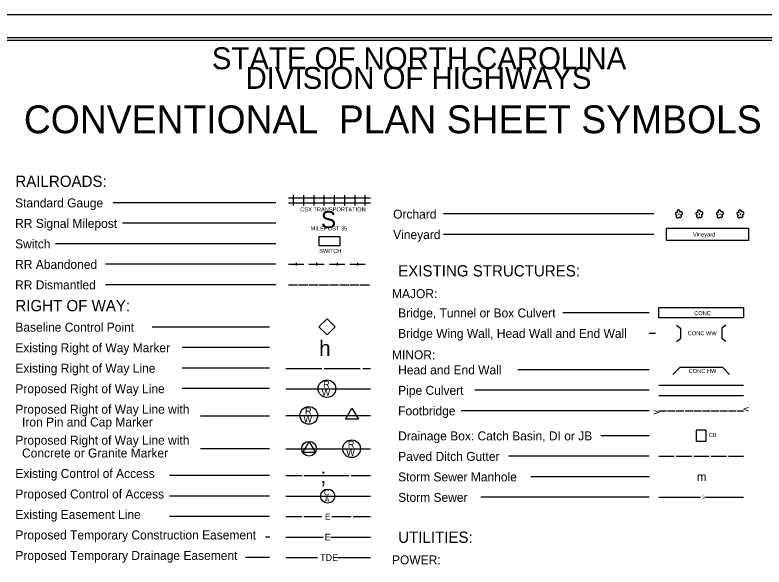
# Model space of a CAD drawing. Extents: x 573853.5 to 573887.1, y -53276.2 to -53254.2.
# Drawn here: x 573864.68 to 573879.29, y -53264.98 to -53254.2 of the extents above; entities that cross this region are included whole.
import ezdxf

# ---------------------------------------------------------------- set-up
doc = ezdxf.new("R2010")
doc.units = 0
for name, color, linetype in [('Default', 7, 'Continuous'), ('Sheet Cutting Line CELL', 7, 'Continuous'), ('Sheet Plot Border Inside CELL', 7, 'Continuous'), ('Sheet Plot Border Outside CELL', 7, 'Continuous'), ('Sheet Symbology CELL', 7, 'Continuous')]:
    doc.layers.add(name, color=color, linetype=linetype)

msp = doc.modelspace()

# ---------------------------------------------------------------- linework, layer by layer
at = {"layer": 'Default'}
msp.add_lwpolyline([(573870.609, -53260.29), (573870.766, -53260.133), (573870.922, -53260.29), (573870.766, -53260.446)], close=True, dxfattribs=at)
at = {"layer": 'Sheet Cutting Line CELL'}
msp.add_line((573887.133, -53254.201), (573853.453, -53254.201), dxfattribs=at)
at = {"layer": 'Sheet Plot Border Inside CELL'}
msp.add_lwpolyline([(573853.713, -53275.752), (573887.043, -53275.752), (573887.043, -53254.65), (573853.713, -53254.65)], close=True, dxfattribs=at)
at = {"layer": 'Sheet Plot Border Outside CELL'}
msp.add_lwpolyline([(573853.453, -53276.201), (573887.133, -53276.201), (573887.133, -53254.201), (573853.453, -53254.201)], close=True, dxfattribs=at)
at = {"layer": 'Sheet Symbology CELL'}
for p, q in [((573870.013, -53257.771), (573870.213, -53257.771)), ((573870.113, -53257.921), (573870.113, -53257.721)), ((573870.213, -53257.771), (573870.413, -53257.771)), ((573870.313, -53257.921), (573870.313, -53257.721)), ((573870.413, -53257.771), (573870.613, -53257.771)), ((573870.513, -53257.921), (573870.513, -53257.721)), ((573870.613, -53257.771), (573870.813, -53257.771)), ((573870.713, -53257.921), (573870.713, -53257.721)), ((573870.813, -53257.771), (573871.013, -53257.771)), ((573870.913, -53257.921), (573870.913, -53257.721)), ((573871.013, -53257.771), (573871.213, -53257.771)), ((573871.113, -53257.921), (573871.113, -53257.721)), ((573871.213, -53257.771), (573871.413, -53257.771)), ((573871.313, -53257.921), (573871.313, -53257.721)), ((573871.413, -53257.771), (573871.613, -53257.771)), ((573871.513, -53257.921), (573871.513, -53257.721)), ((573869.765, -53257.866), (573866.597, -53257.866)), ((573870.013, -53257.871), (573870.213, -53257.871)), ((573870.213, -53257.871), (573870.413, -53257.871)), ((573870.413, -53257.871), (573870.613, -53257.871)), ((573870.613, -53257.871), (573870.813, -53257.871)), ((573870.813, -53257.871), (573871.013, -53257.871)), ((573871.013, -53257.871), (573871.213, -53257.871)), ((573871.213, -53257.871), (573871.413, -53257.871)), ((573871.413, -53257.871), (573871.613, -53257.871)), ((573877.139, -53258.085), (573873.041, -53258.085)), ((573869.765, -53258.266), (573866.774, -53258.266)), ((573877.139, -53258.485), (573873.041, -53258.485)), ((573869.765, -53258.666), (573865.467, -53258.666)), ((573869.765, -53259.066), (573866.442, -53259.066)), ((573870.013, -53259.066), (573870.313, -53259.066)), ((573870.163, -53259.041), (573870.163, -53259.091)), ((573870.413, -53259.066), (573870.713, -53259.066)), ((573870.563, -53259.041), (573870.563, -53259.091)), ((573870.813, -53259.066), (573871.113, -53259.066)), ((573870.963, -53259.041), (573870.963, -53259.091)), ((573871.213, -53259.066), (573871.513, -53259.066)), ((573871.363, -53259.041), (573871.363, -53259.091)), ((573869.765, -53259.466), (573866.442, -53259.466)), ((573869.765, -53259.466), (573866.442, -53259.466)), ((573870.013, -53259.466), (573870.193, -53259.466)), ((573870.213, -53259.466), (573870.393, -53259.466)), ((573870.413, -53259.466), (573870.593, -53259.466)), ((573870.613, -53259.466), (573870.793, -53259.466)), ((573870.813, -53259.466), (573870.993, -53259.466)), ((573871.013, -53259.466), (573871.193, -53259.466)), ((573871.213, -53259.466), (573871.393, -53259.466)), ((573871.413, -53259.466), (573871.593, -53259.466)), ((573877.053, -53260.014), (573875.365, -53260.014)), ((573869.642, -53260.293), (573867.358, -53260.293)), ((573877.582, -53260.257), (573877.664, -53260.314)), ((573877.664, -53260.314), (573877.664, -53260.514)), ((573878.546, -53260.257), (573878.464, -53260.314)), ((573878.464, -53260.314), (573878.464, -53260.514)), ((573877.053, -53260.414), (573877.173, -53260.414)), ((573877.582, -53260.572), (573877.664, -53260.514)), ((573878.546, -53260.572), (573878.464, -53260.514)), ((573869.642, -53260.693), (573867.943, -53260.693)), ((573869.642, -53261.093), (573867.943, -53261.093)), ((573869.963, -53261.105), (573870.663, -53261.105)), ((573870.713, -53261.105), (573871.413, -53261.105)), ((573871.463, -53261.105), (573871.613, -53261.105)), ((573877.053, -53261.126), (573874.487, -53261.126)), ((573877.51, -53261.217), (573877.652, -53261.076)), ((573877.652, -53261.076), (573878.477, -53261.076)), ((573878.477, -53261.076), (573878.618, -53261.217)), ((573869.642, -53261.493), (573867.943, -53261.493)), ((573869.963, -53261.496), (573871.613, -53261.496)), ((573877.239, -53261.426), (573878.889, -53261.426)), ((573877.053, -53261.526), (573873.649, -53261.526)), ((573877.239, -53261.626), (573878.889, -53261.626)), ((573877.053, -53261.926), (573873.384, -53261.926)), ((573877.239, -53261.926), (573877.389, -53261.926)), ((573877.409, -53261.926), (573877.559, -53261.926)), ((573877.579, -53261.926), (573877.729, -53261.926)), ((573877.749, -53261.926), (573877.899, -53261.926)), ((573877.919, -53261.926), (573878.069, -53261.926)), ((573878.089, -53261.926), (573878.239, -53261.926)), ((573878.259, -53261.926), (573878.409, -53261.926)), ((573878.429, -53261.926), (573878.579, -53261.926)), ((573878.599, -53261.926), (573878.749, -53261.926)), ((573878.769, -53261.926), (573878.889, -53261.926)), ((573869.642, -53262.03), (573868.3, -53262.03)), ((573869.963, -53262.018), (573871.613, -53262.018)), ((573871.252, -53262.018), (573871.252, -53262.018)), ((573877.053, -53262.414), (573876.109, -53262.414)), ((573869.642, -53262.671), (573868.3, -53262.671)), ((573869.963, -53262.668), (573871.613, -53262.668)), ((573870.417, -53262.668), (573870.417, -53262.668)), ((573877.053, -53262.814), (573874.314, -53262.814)), ((573877.239, -53262.814), (573877.539, -53262.814)), ((573877.579, -53262.814), (573877.879, -53262.814)), ((573877.919, -53262.814), (573878.219, -53262.814)), ((573878.259, -53262.814), (573878.559, -53262.814)), ((573878.599, -53262.814), (573878.889, -53262.814)), ((573869.642, -53263.193), (573867.691, -53263.193)), ((573869.963, -53263.193), (573870.272, -53263.193)), ((573870.312, -53263.193), (573871.2, -53263.193)), ((573871.24, -53263.193), (573871.613, -53263.193)), ((573877.053, -53263.214), (573874.74, -53263.214)), ((573869.642, -53263.593), (573867.691, -53263.593)), ((573869.963, -53263.593), (573871.613, -53263.593)), ((573877.053, -53263.614), (573873.769, -53263.614)), ((573877.239, -53263.614), (573878.05, -53263.614)), ((573878.15, -53263.614), (573878.889, -53263.614)), ((573869.642, -53263.993), (573867.691, -53263.993)), ((573869.963, -53263.993), (573870.273, -53263.993)), ((573870.313, -53263.993), (573870.663, -53263.993)), ((573870.863, -53263.993), (573871.238, -53263.993)), ((573871.278, -53263.993), (573871.613, -53263.993)), ((573869.65, -53264.393), (573869.566, -53264.393)), ((573869.963, -53264.393), (573870.015, -53264.393)), ((573870.015, -53264.393), (573870.69, -53264.393)), ((573870.84, -53264.393), (573871.515, -53264.393)), ((573871.515, -53264.393), (573871.613, -53264.393)), ((573869.642, -53264.793), (573869.179, -53264.793)), ((573869.963, -53264.793), (573870.03, -53264.793)), ((573870.03, -53264.793), (573870.58, -53264.793)), ((573870.98, -53264.793), (573871.53, -53264.793)), ((573871.53, -53264.793), (573871.613, -53264.793))]:
    msp.add_line(p, q, dxfattribs=at)
for points in [[(573886.793, -53254.701), (573856.793, -53254.701), (573856.793, -53275.68), (573886.793, -53275.68)], [(573870.613, -53258.527), (573871.013, -53258.527), (573871.013, -53258.709), (573870.613, -53258.709)], [(573871.127, -53262.09), (573871.252, -53261.874), (573871.377, -53262.09)], [(573877.968, -53262.521), (573878.16, -53262.521), (573878.16, -53262.308), (573877.968, -53262.308)], [(573870.292, -53262.74), (573870.417, -53262.524), (573870.542, -53262.74)]]:
    msp.add_lwpolyline(points, close=True, dxfattribs=at)
for points in [[(573877.648, -53258.05), (573877.651, -53258.044), (573877.652, -53258.038), (573877.651, -53258.032), (573877.65, -53258.026), (573877.647, -53258.021), (573877.644, -53258.016), (573877.639, -53258.012), (573877.634, -53258.009), (573877.627, -53258.007), (573877.622, -53258.007), (573877.616, -53258.008), (573877.61, -53258.01), (573877.605, -53258.013), (573877.6, -53258.017), (573877.597, -53258.023), (573877.595, -53258.028), (573877.594, -53258.034), (573877.594, -53258.04), (573877.595, -53258.046), (573877.598, -53258.051), (573877.602, -53258.057), (573877.597, -53258.054), (573877.591, -53258.053), (573877.585, -53258.053), (573877.58, -53258.055), (573877.575, -53258.057), (573877.57, -53258.061), (573877.566, -53258.065), (573877.563, -53258.07), (573877.562, -53258.075), (573877.561, -53258.082), (573877.562, -53258.087), (573877.564, -53258.092), (573877.568, -53258.097), (573877.571, -53258.101), (573877.576, -53258.104), (573877.582, -53258.107), (573877.587, -53258.108), (573877.593, -53258.108), (573877.588, -53258.11), (573877.583, -53258.114), (573877.58, -53258.118), (573877.578, -53258.124), (573877.576, -53258.13), (573877.576, -53258.135), (573877.577, -53258.141), (573877.58, -53258.146), (573877.583, -53258.151), (573877.587, -53258.155), (573877.592, -53258.158), (573877.597, -53258.16), (573877.603, -53258.16), (573877.609, -53258.16), (573877.614, -53258.159), (573877.619, -53258.155), (573877.624, -53258.152), (573877.629, -53258.143)], [(573877.631, -53258.085), (573877.628, -53258.085), (573877.626, -53258.086), (573877.624, -53258.087), (573877.624, -53258.09), (573877.624, -53258.092), (573877.626, -53258.094), (573877.629, -53258.094), (573877.631, -53258.094), (573877.633, -53258.092), (573877.634, -53258.089), (573877.633, -53258.087), (573877.631, -53258.085)], [(573877.629, -53258.143), (573877.641, -53258.15), (573877.647, -53258.152), (573877.653, -53258.153), (573877.659, -53258.152), (573877.664, -53258.15), (573877.669, -53258.147), (573877.674, -53258.143), (573877.677, -53258.138), (573877.679, -53258.133), (573877.681, -53258.127), (573877.68, -53258.121), (573877.679, -53258.115), (573877.675, -53258.109), (573877.672, -53258.105), (573877.667, -53258.102), (573877.661, -53258.099), (573877.667, -53258.1), (573877.674, -53258.1), (573877.679, -53258.098), (573877.685, -53258.095), (573877.69, -53258.092), (573877.694, -53258.087), (573877.697, -53258.081), (573877.698, -53258.075), (573877.699, -53258.069), (573877.698, -53258.063), (573877.696, -53258.057), (573877.692, -53258.052), (573877.687, -53258.047), (573877.682, -53258.044), (573877.676, -53258.042), (573877.67, -53258.041), (573877.664, -53258.041), (573877.658, -53258.043), (573877.653, -53258.046), (573877.648, -53258.05)], [(573878.048, -53258.05), (573878.051, -53258.044), (573878.052, -53258.038), (573878.051, -53258.032), (573878.05, -53258.026), (573878.047, -53258.021), (573878.044, -53258.016), (573878.039, -53258.012), (573878.034, -53258.009), (573878.027, -53258.007), (573878.022, -53258.007), (573878.016, -53258.008), (573878.01, -53258.01), (573878.005, -53258.013), (573878, -53258.017), (573877.997, -53258.023), (573877.995, -53258.028), (573877.994, -53258.034), (573877.994, -53258.04), (573877.995, -53258.046), (573877.998, -53258.051), (573878.002, -53258.057), (573877.997, -53258.054), (573877.991, -53258.053), (573877.985, -53258.053), (573877.98, -53258.055), (573877.975, -53258.057), (573877.97, -53258.061), (573877.966, -53258.065), (573877.963, -53258.07), (573877.962, -53258.075), (573877.961, -53258.082), (573877.962, -53258.087), (573877.964, -53258.092), (573877.968, -53258.097), (573877.971, -53258.101), (573877.976, -53258.104), (573877.982, -53258.107), (573877.987, -53258.108), (573877.993, -53258.108), (573877.988, -53258.11), (573877.983, -53258.114), (573877.98, -53258.118), (573877.978, -53258.124), (573877.976, -53258.13), (573877.976, -53258.135), (573877.977, -53258.141), (573877.98, -53258.146), (573877.983, -53258.151), (573877.987, -53258.155), (573877.992, -53258.158), (573877.997, -53258.16), (573878.003, -53258.16), (573878.009, -53258.16), (573878.014, -53258.159), (573878.019, -53258.155), (573878.024, -53258.152), (573878.029, -53258.143)], [(573878.031, -53258.085), (573878.028, -53258.085), (573878.026, -53258.086), (573878.024, -53258.087), (573878.024, -53258.09), (573878.024, -53258.092), (573878.026, -53258.094), (573878.029, -53258.094), (573878.031, -53258.094), (573878.033, -53258.092), (573878.034, -53258.089), (573878.033, -53258.087), (573878.031, -53258.085)], [(573878.029, -53258.143), (573878.041, -53258.15), (573878.047, -53258.152), (573878.053, -53258.153), (573878.059, -53258.152), (573878.064, -53258.15), (573878.069, -53258.147), (573878.074, -53258.143), (573878.077, -53258.138), (573878.079, -53258.133), (573878.081, -53258.127), (573878.08, -53258.121), (573878.079, -53258.115), (573878.075, -53258.109), (573878.072, -53258.105), (573878.067, -53258.102), (573878.061, -53258.099), (573878.067, -53258.1), (573878.074, -53258.1), (573878.079, -53258.098), (573878.085, -53258.095), (573878.09, -53258.092), (573878.094, -53258.087), (573878.097, -53258.081), (573878.098, -53258.075), (573878.099, -53258.069), (573878.098, -53258.063), (573878.096, -53258.057), (573878.092, -53258.052), (573878.087, -53258.047), (573878.082, -53258.044), (573878.076, -53258.042), (573878.07, -53258.041), (573878.064, -53258.041), (573878.058, -53258.043), (573878.053, -53258.046), (573878.048, -53258.05)], [(573878.448, -53258.05), (573878.451, -53258.044), (573878.452, -53258.038), (573878.451, -53258.032), (573878.45, -53258.026), (573878.447, -53258.021), (573878.444, -53258.016), (573878.439, -53258.012), (573878.434, -53258.009), (573878.427, -53258.007), (573878.422, -53258.007), (573878.416, -53258.008), (573878.41, -53258.01), (573878.405, -53258.013), (573878.4, -53258.017), (573878.397, -53258.023), (573878.395, -53258.028), (573878.394, -53258.034), (573878.394, -53258.04), (573878.395, -53258.046), (573878.398, -53258.051), (573878.402, -53258.057), (573878.397, -53258.054), (573878.391, -53258.053), (573878.385, -53258.053), (573878.38, -53258.055), (573878.375, -53258.057), (573878.37, -53258.061), (573878.366, -53258.065), (573878.363, -53258.07), (573878.362, -53258.075), (573878.361, -53258.082), (573878.362, -53258.087), (573878.364, -53258.092), (573878.368, -53258.097), (573878.371, -53258.101), (573878.376, -53258.104), (573878.382, -53258.107), (573878.387, -53258.108), (573878.393, -53258.108), (573878.388, -53258.11), (573878.383, -53258.114), (573878.38, -53258.118), (573878.378, -53258.124), (573878.376, -53258.13), (573878.376, -53258.135), (573878.377, -53258.141), (573878.38, -53258.146), (573878.383, -53258.151), (573878.387, -53258.155), (573878.392, -53258.158), (573878.397, -53258.16), (573878.403, -53258.16), (573878.409, -53258.16), (573878.414, -53258.159), (573878.419, -53258.155), (573878.424, -53258.152), (573878.429, -53258.143)], [(573878.431, -53258.085), (573878.428, -53258.085), (573878.426, -53258.086), (573878.424, -53258.087), (573878.424, -53258.09), (573878.424, -53258.092), (573878.426, -53258.094), (573878.429, -53258.094), (573878.431, -53258.094), (573878.433, -53258.092), (573878.434, -53258.089), (573878.433, -53258.087), (573878.431, -53258.085)], [(573878.429, -53258.143), (573878.441, -53258.15), (573878.447, -53258.152), (573878.453, -53258.153), (573878.459, -53258.152), (573878.464, -53258.15), (573878.469, -53258.147), (573878.474, -53258.143), (573878.477, -53258.138), (573878.479, -53258.133), (573878.481, -53258.127), (573878.48, -53258.121), (573878.479, -53258.115), (573878.475, -53258.109), (573878.472, -53258.105), (573878.467, -53258.102), (573878.461, -53258.099), (573878.467, -53258.1), (573878.474, -53258.1), (573878.479, -53258.098), (573878.485, -53258.095), (573878.49, -53258.092), (573878.494, -53258.087), (573878.497, -53258.081), (573878.498, -53258.075), (573878.499, -53258.069), (573878.498, -53258.063), (573878.496, -53258.057), (573878.492, -53258.052), (573878.487, -53258.047), (573878.482, -53258.044), (573878.476, -53258.042), (573878.47, -53258.041), (573878.464, -53258.041), (573878.458, -53258.043), (573878.453, -53258.046), (573878.448, -53258.05)], [(573878.848, -53258.05), (573878.851, -53258.044), (573878.852, -53258.038), (573878.851, -53258.032), (573878.85, -53258.026), (573878.847, -53258.021), (573878.844, -53258.016), (573878.839, -53258.012), (573878.834, -53258.009), (573878.827, -53258.007), (573878.822, -53258.007), (573878.816, -53258.008), (573878.81, -53258.01), (573878.805, -53258.013), (573878.8, -53258.017), (573878.797, -53258.023), (573878.795, -53258.028), (573878.794, -53258.034), (573878.794, -53258.04), (573878.795, -53258.046), (573878.798, -53258.051), (573878.802, -53258.057), (573878.797, -53258.054), (573878.791, -53258.053), (573878.785, -53258.053), (573878.78, -53258.055), (573878.775, -53258.057), (573878.77, -53258.061), (573878.766, -53258.065), (573878.763, -53258.07), (573878.762, -53258.075), (573878.761, -53258.082), (573878.762, -53258.087), (573878.764, -53258.092), (573878.768, -53258.097), (573878.771, -53258.101), (573878.776, -53258.104), (573878.782, -53258.107), (573878.787, -53258.108), (573878.793, -53258.108), (573878.788, -53258.11), (573878.783, -53258.114), (573878.78, -53258.118), (573878.778, -53258.124), (573878.776, -53258.13), (573878.776, -53258.135), (573878.777, -53258.141), (573878.78, -53258.146), (573878.783, -53258.151), (573878.787, -53258.155), (573878.792, -53258.158), (573878.797, -53258.16), (573878.803, -53258.16), (573878.809, -53258.16), (573878.814, -53258.159), (573878.819, -53258.155), (573878.824, -53258.152), (573878.829, -53258.143)], [(573878.831, -53258.085), (573878.828, -53258.085), (573878.826, -53258.086), (573878.824, -53258.087), (573878.824, -53258.09), (573878.824, -53258.092), (573878.826, -53258.094), (573878.829, -53258.094), (573878.831, -53258.094), (573878.833, -53258.092), (573878.834, -53258.089), (573878.833, -53258.087), (573878.831, -53258.085)], [(573878.829, -53258.143), (573878.841, -53258.15), (573878.847, -53258.152), (573878.853, -53258.153), (573878.859, -53258.152), (573878.864, -53258.15), (573878.869, -53258.147), (573878.874, -53258.143), (573878.877, -53258.138), (573878.879, -53258.133), (573878.881, -53258.127), (573878.88, -53258.121), (573878.879, -53258.115), (573878.875, -53258.109), (573878.872, -53258.105), (573878.867, -53258.102), (573878.861, -53258.099), (573878.867, -53258.1), (573878.874, -53258.1), (573878.879, -53258.098), (573878.885, -53258.095), (573878.89, -53258.092), (573878.894, -53258.087), (573878.897, -53258.081), (573878.898, -53258.075), (573878.899, -53258.069), (573878.898, -53258.063), (573878.896, -53258.057), (573878.892, -53258.052), (573878.887, -53258.047), (573878.882, -53258.044), (573878.876, -53258.042), (573878.87, -53258.041), (573878.864, -53258.041), (573878.858, -53258.043), (573878.853, -53258.046), (573878.848, -53258.05)], [(573877.387, -53258.365), (573878.987, -53258.365), (573878.987, -53258.605), (573877.387, -53258.605), (573877.387, -53258.365)], [(573877.239, -53259.914), (573878.889, -53259.914), (573878.889, -53260.114), (573877.239, -53260.114), (573877.239, -53259.914)]]:
    msp.add_lwpolyline(points, dxfattribs=at)
for centre, radius in [((573870.765, -53261.496), 0.172), ((573870.411, -53262.018), 0.172), ((573870.417, -53262.668), 0.144), ((573871.245, -53262.668), 0.172), ((573870.78, -53263.593), 0.138)]:
    msp.add_circle(centre, radius, dxfattribs=at)

# ---------------------------------------------------------------- texts
for s, height, p in [('STATE OF NORTH CAROLINA', 0.42838, (573868.519, -53255.26)), ('DIVISION OF HIGHWAYS', 0.42838, (573869.176, -53255.643)), ('CONVENTIONAL  PLAN SHEET SYMBOLS', 0.54401, (573864.853, -53256.51)), ('RAILROADS:', 0.22, (573864.687, -53257.557)), ('Standard Gauge', 0.175, (573864.682, -53257.957)), ('Orchard', 0.175, (573872.056, -53258.176)), ('S', 0.33, (573870.648, -53258.359)), ('RR Signal Milepost', 0.175, (573864.682, -53258.357)), ('Vineyard', 0.175, (573872.056, -53258.576)), ('Switch', 0.175, (573864.682, -53258.757)), ('RR Abandoned', 0.175, (573864.682, -53259.157)), ('EXISTING STRUCTURES:', 0.22, (573872.154, -53259.305)), ('RR Dismantled', 0.175, (573864.682, -53259.557)), ('MAJOR:', 0.175, (573872.033, -53259.728)), ('RIGHT OF WAY:', 0.22, (573864.687, -53259.984)), ('Bridge, Tunnel or Box Culvert', 0.175, (573872.154, -53260.105)), ('CONC', 0.08, (573877.928, -53260.062)), ('Baseline Control Point', 0.175, (573864.687, -53260.384)), ('Bridge Wing Wall, Head Wall and End Wall', 0.175, (573872.154, -53260.505)), ('Existing Right of Way Marker', 0.175, (573864.687, -53260.784)), ('h', 0.3, (573870.613, -53260.855)), ('MINOR:', 0.175, (573872.033, -53260.922)), ('Existing Right of Way Line', 0.175, (573864.687, -53261.184)), ('Head and End Wall', 0.175, (573872.154, -53261.217)), ('R', 0.135, (573870.691, -53261.476)), ('Proposed Right of Way Line', 0.175, (573864.687, -53261.584)), ('W', 0.135, (573870.66, -53261.635)), ('Pipe Culvert', 0.175, (573872.154, -53261.616)), ('Proposed Right of Way Line with', 0.175, (573864.687, -53261.984)), ('R', 0.135, (573870.337, -53261.998)), ('Footbridge', 0.175, (573872.154, -53262.016)), ('  Iron Pin and Cap Marker', 0.175, (573864.687, -53262.234)), ('W', 0.135, (573870.306, -53262.157)), ('Drainage Box: Catch Basin, DI or JB', 0.175, (573872.154, -53262.505)), ('Proposed Right of Way Line with', 0.175, (573864.687, -53262.589)), ('R', 0.135, (573871.171, -53262.648)), ('  Concrete or Granite Marker', 0.175, (573864.687, -53262.839)), ('W', 0.135, (573871.14, -53262.807)), ('Paved Ditch Gutter', 0.175, (573872.154, -53262.905)), ('Existing Control of Access', 0.175, (573864.687, -53263.239)), (';', 0.3, (573870.638, -53263.343)), ('Storm Sewer Manhole', 0.175, (573872.154, -53263.305)), ('m', 0.165, (573877.982, -53263.297)), ('Proposed Control of Access', 0.175, (573864.687, -53263.639)), ('C', 0.108, (573870.707, -53263.577)), ('Storm Sewer', 0.175, (573872.154, -53263.705)), ('A', 0.108, (573870.718, -53263.707)), ('S', 0.06, (573878.082, -53263.644)), ('Existing Easement Line', 0.175, (573864.687, -53264.039)), ('E', 0.12, (573870.727, -53264.053)), ('Proposed Temporary Construction Easement', 0.175, (573864.687, -53264.439)), ('UTILITIES:', 0.22, (573872.154, -53264.505)), ('E', 0.131, (573870.722, -53264.459)), ('Proposed Temporary Drainage Easement', 0.175, (573864.687, -53264.839)), ('TDE', 0.131, (573870.632, -53264.859)), ('POWER:', 0.175, (573872.033, -53264.925))]:
    msp.add_text(s, height=height, dxfattribs=at).set_placement(p)
for s, height, rotation, p in [('CSX TRANSPORTATION', 0.08, 360, (573870.244, -53258.036)), ('MILEPOST 35', 0.08, 360, (573870.448, -53258.407)), ('Vineyard', 0.08, 0, (573877.904, -53258.525)), ('SWITCH', 0.08, 360, (573870.612, -53258.847)), ('CONC WW', 0.08, 0, (573877.802, -53260.454)), ('CONC HW', 0.08, 360, (573877.82, -53261.189)), ('v', 0.132, 89.7591, (573877.239, -53262)), ('v', 0.132, 270.2409, (573878.889, -53261.851)), ('CB', 0.08, 360, (573878.213, -53262.438))]:
    msp.add_text(s, height=height, rotation=rotation, dxfattribs=at).set_placement(p)

doc.saveas('drawing.dxf')
